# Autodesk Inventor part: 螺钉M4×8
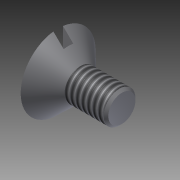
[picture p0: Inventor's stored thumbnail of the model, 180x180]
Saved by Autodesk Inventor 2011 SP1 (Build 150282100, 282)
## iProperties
Created: 2013-12
Part Number: 螺钉M4×8
Document SubType Name: Modeling
Designer: Administrator
Density: 1 g/cm^3
Author: Administrator
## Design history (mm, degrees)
sketch "草图1"
  geometry: L1 (0, 0)-(2.8, 0); L2 (2.8, 0)-(2.8, 2); L3 (0, 0)-(0, 4.7); L4 (0, 4.7)-(2.8, 2); L5 (-0.56, 0)-(3.36, 0) reference
  constraints: 8 end point, 1 horizontal, 1 parallel, 1 perpendicular
  dimensions: "d0" = 2.8 distance of L1.start L1.end; "d1" = 2 distance of L1.end L2.end; "d2" = 4.7 distance of L1.start L3.end
revolve "旋转1" sketch "草图1" stored, may be unused: angle "d3" = 90 deg
sketch "草图2"
  geometry: L1 (-4.7, 0.6)-(4.7, 0.6); L2 (4.7, 0.6)-(4.7, -0.6); L3 (4.7, -0.6)-(-4.7, -0.6); L4 (-4.7, -0.6)-(-4.7, 0.6); C1 r 4.7 at (0, 0) reference; 2 further points
  constraints: 8 end point, 2 midpoint, 2 parallel, 1 horizontal, 1 horizontal alignment, 1 perpendicular, 1 vertical alignment
  dimensions: "d4" = 9.4 distance of L1.start L1.end; "d5" = 1.2 distance of L1.end L2.end
extrude "拉伸1" cut sketch "草图2" distance "d6" = 1.3; taper "d7" = 0 deg
sketch "草图3"
  geometry: C1 r 2 at (0, 0) reference
extrude "拉伸2" join sketch "草图3" distance "d8" = 5.2; taper "d9" = 0 deg
feature "螺纹1" dims "d10" = 10, "d11" = 0
chamfer "倒角1" distance "d12" = 0.3; stored, may be unused: second distance "d13" = 2, angle "d14" = 45 deg
node "实体1"
